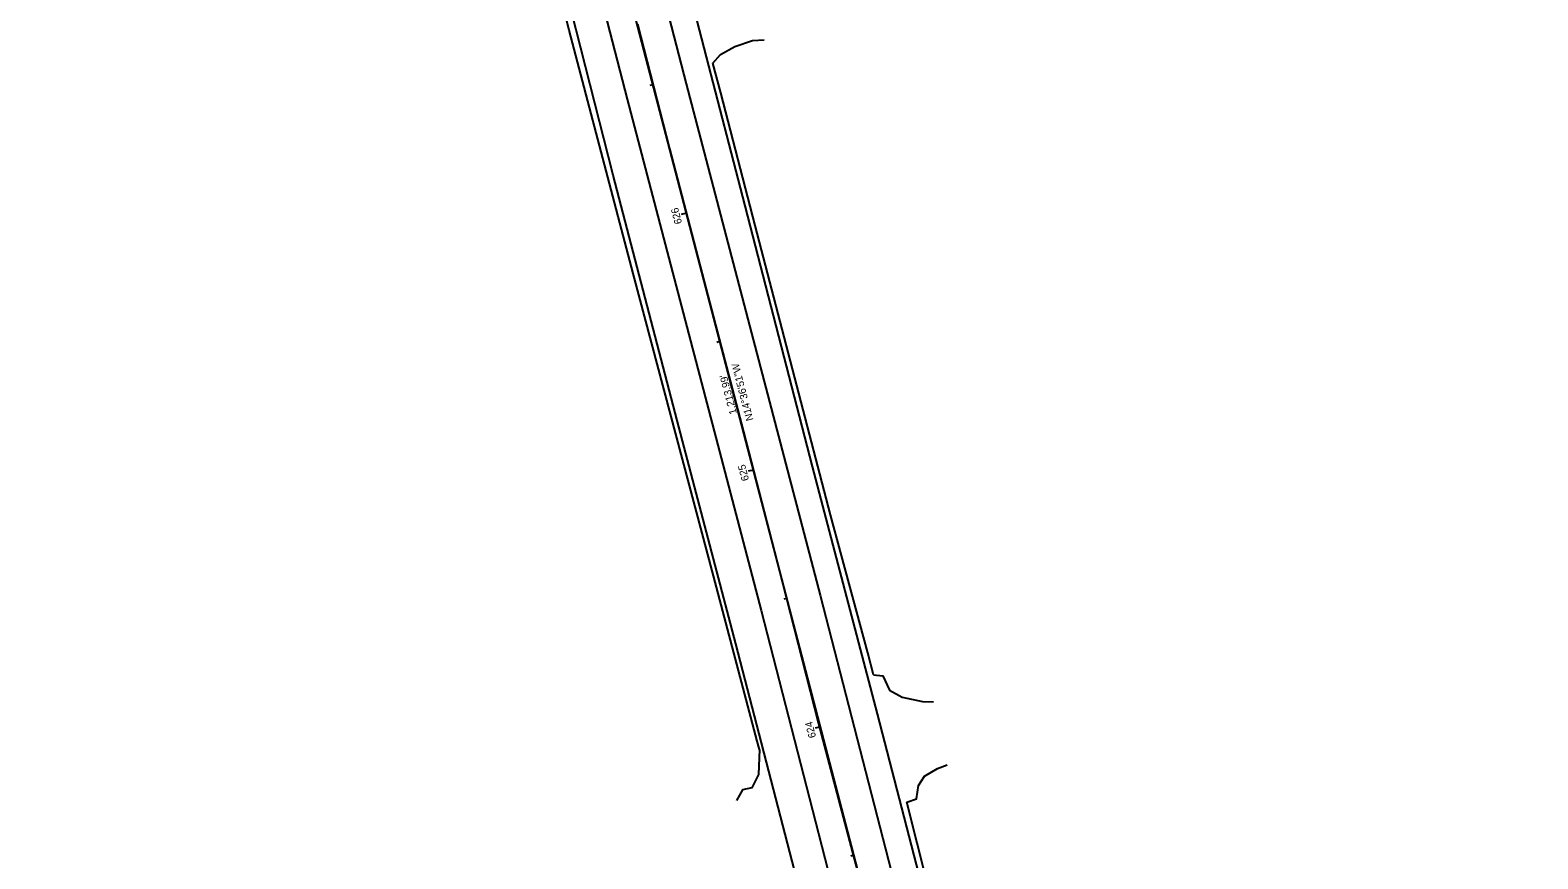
# Model space of a CAD drawing. Extents: x 171274 to 172251, y 454256 to 458569.
# Drawn here: x 171284 to 171851, y 455066 to 455378 of the extents above; entities that cross this region are included whole.
import ezdxf

# ---------------------------------------------------------------- set-up
doc = ezdxf.new("R2010")
doc.units = 0
for name, color, linetype in [('_CIVIL_CONSTRUCTION', 7, 'Continuous'), ('BR_P_Gen_Waterproofing', 7, 'Continuous'), ('BR_X_Brg_Pad_Object', 7, 'Continuous'), ('BR_X_Gen_Approach_Slab', 7, 'Continuous'), ('PV_P_Saw_Cut_Line', 7, 'Continuous'), ('SC_Scratch2', 7, 'Continuous'), ('UT_X_Water_Cells', 7, 'Continuous'), ('VG_X_Shrub_Line_Lt', 7, 'Continuous'), ('VG_X_Shrub_Line_Rt', 7, 'Continuous')]:
    doc.layers.add(name, color=color, linetype=linetype)

msp = doc.modelspace()

# ---------------------------------------------------------------- linework, layer by layer
at = {"layer": '_CIVIL_CONSTRUCTION'}
for q in [(171283.69, 456257.09), (171395.21, 455829.41)]:
    msp.add_line((171701.51, 454654.7), q, dxfattribs=at)
at = {"layer": 'BR_X_Brg_Pad_Object'}
for points in [[(171754.03, 454407.86), (171735.92, 454461.96), (171723.94, 454498.82), (171703.07, 454565.09), (171686.66, 454622.59), (171676.14, 454661.67), (171658.11, 454727.95), (171638.56, 454802.49), (171614.12, 454897.2), (171594.66, 454972.24), (171569.68, 455068.83), (171549.4, 455147.21), (171527.32, 455231.4), (171503.18, 455323.76), (171475.49, 455432.87)], [(171851.36, 454270.04), (171826.95, 454336.46), (171804.15, 454399.96), (171781.51, 454465.56), (171759.43, 454534.2), (171739.13, 454601.5), (171724.17, 454654.59), (171697.86, 454754.34), (171674.05, 454845.45), (171644.56, 454959.64), (171620.14, 455053.46), (171602.68, 455120.89), (171578.31, 455214), (171552.92, 455312.25), (171527.2, 455411.62)]]:
    msp.add_lwpolyline(points, dxfattribs=at)
at = {"layer": 'BR_X_Gen_Approach_Slab'}
msp.add_lwpolyline([(171512.39, 455380.78), (171524.4, 455333.79), (171537.46, 455283.68), (171552.29, 455227.08), (171566.86, 455170.72), (171580.41, 455117.68), (171606.22, 455019.64), (171627.99, 454934.06), (171642.91, 454879.06), (171657.04, 454823.08), (171672.85, 454761.75), (171721.65, 454581.79), (171745.19, 454504.77), (171770.62, 454429.36), (171804.38, 454335.27), (171829.88, 454266.23)], dxfattribs=at)
at = {"layer": 'PV_P_Saw_Cut_Line'}
for points in [[(171558.29, 455107.46), (171557.48, 455110.64), (171540.93, 455172.92), (171510.71, 455286.81), (171486.61, 455378.45), (171470.46, 455441.39), (171454.22, 455507.71), (171429.71, 455601.02), (171414.88, 455651.31), (171387.7, 455745.41), (171360.93, 455847.8), (171341.64, 455927.77), (171327.71, 456008.91), (171320.5, 456092.02), (171319.84, 456141.55), (171327.18, 456222.76), (171334.15, 456270.38), (171334.45, 456271.77)], [(171601.28, 455135.54), (171599.12, 455143.82), (171585.08, 455195.83), (171572.38, 455244.56), (171556.69, 455304.86), (171543.71, 455354.86), (171540.79, 455366.02)], [(171684.91, 454815.49), (171677.37, 454844.17), (171662.17, 454898.71), (171651.19, 454943.5), (171639.62, 454987.27), (171625.55, 455040.8), (171613.74, 455087.62)]]:
    msp.add_lwpolyline(points, dxfattribs=at)
at = {"layer": 'SC_Scratch2'}
for points in [[(171472.94, 455579.79), (171492.29, 455506.9), (171530.75, 455358.19), (171581.19, 455165.63), (171667.81, 454828.72), (171739.52, 454564.63), (171774.65, 454453.78), (171842.22, 454266.94)], [(171470.04, 455501.07), (171508.5, 455352.39), (171558.93, 455159.85), (171645.58, 454822.85), (171717.45, 454558.14), (171752.87, 454446.4), (171820.59, 454259.11)]]:
    msp.add_lwpolyline(points, dxfattribs=at)
at = {"layer": 'UT_X_Water_Cells'}
for points in [[(171540.79, 455366.02), (171543.65, 455369.22), (171549.06, 455372.29), (171555.64, 455374.55), (171560.04, 455374.77)], [(171601.28, 455135.54), (171604.72, 455135.23), (171607.29, 455129.81), (171611.96, 455127.2), (171619.62, 455125.47), (171623.86, 455125.41)], [(171558.29, 455107.46), (171557.91, 455098.04), (171555.41, 455093), (171551.9, 455092.21), (171549.59, 455088.2)], [(171613.74, 455087.62), (171617.46, 455088.84), (171618.19, 455093.85), (171620.41, 455097.35), (171625.38, 455100.35), (171628.98, 455101.65)]]:
    msp.add_lwpolyline(points, dxfattribs=at)
at = {"layer": 'VG_X_Shrub_Line_Lt'}
for p, q in [((171518.16, 455357.88), (171517, 455357.58)), ((171530.77, 455309.5), (171528.84, 455309)), ((171543.39, 455261.12), (171542.23, 455260.81)), ((171556, 455212.73), (171554.07, 455212.23)), ((171568.62, 455164.35), (171567.46, 455164.05)), ((171581.23, 455115.97), (171579.3, 455115.47)), ((171593.85, 455067.59), (171592.69, 455067.29))]:
    msp.add_line(p, q, dxfattribs=at)

# ---------------------------------------------------------------- texts
at = {"layer": 'BR_P_Gen_Waterproofing'}
msp.add_text('N14°36\'51"W', height=2.8, rotation=104.6143, dxfattribs=at).set_placement((171556.04, 455231.63))
at = {"layer": 'VG_X_Shrub_Line_Lt'}
for s, p in [('626', (171529.17, 455305.72)), ('625', (171554.39, 455209)), ('624', (171579.64, 455112.17))]:
    msp.add_text(s, height=2.8, rotation=104.6143, dxfattribs=at).set_placement(p)
at = {"layer": 'VG_X_Shrub_Line_Rt'}
msp.add_text("1,213.99'", height=2.8, rotation=104.6143, dxfattribs=at).set_placement((171549.8, 455234.07))

doc.saveas('drawing.dxf')
